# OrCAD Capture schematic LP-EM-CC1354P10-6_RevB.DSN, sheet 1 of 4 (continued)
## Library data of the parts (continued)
L12 L13 = INDUCTOR: INDUCTOR, RF, CHIP, NON-MAGNETIC CORE, 3.7nH, -0.1nH/+0.1nH, 0.4A, -55DEGC/+125DEGC, 0201, SMD; ALT_SYMBOLS: INDC0603X33A2L,INDC0603X33A2M; Additional Datasheet URL: https://search.murata.co.jp/Ceramy/image/img/P02/JELF243C-0015.pdf; AutoDoc File: https://notefied-dynamic-precision.com/DB/Apps/Desktop/Item/Object.aspx?id=97117; BU Name: DYNAMIC PRECISION GDANSK; Budget Currency: EUR; Budget Price: 0.03371; Client Status: UNDER_REVIEW; Core Material: NON-MAGNETIC; Country of Origin: Missing Info; Datasheet URL: https://www.murata.com/-/media/webrenewal/support/library/catalog/products/inductor/chip/o05e.ashx?la=en-gb; Datasheet URL 1: http://psearch.murata.com/inductor/product/LQP03TN2N4B02%23.pdf; Datasheet URL 2: http://www.murata.com/~/media/webrenewal/support/library/catalog/products/inductor/chip/o05e.ashx; Frequency: 6GHz; Mass: 0.0002g; Max Oper Temp: +125DEGC; Max Tol: +0.1nH; Maximum Operating Temperature: +125DEGC; Maximum Tolerance: +0.1nH; Min Oper Temp: -55DEGC; Min Tol: -0.1nH; Minimum Operating Temperature: -55DEGC; Minimum Tolerance: -0.1nH; Mounting Type: SMD; NOTEfied URL: https://notefied-dynamic-precision.com/NOTEfiedWebInterface/part/show?partNumber=03-06940; PCB Package: 0201; Packing Size: 50000; Packing Type: Tape & Reel; Part Number: 03-06940; Part Type: Inductor|RF|CHIP|0201; ROHS: Compliant; Resistance: 0.3; Revision: R020; RoHS Status: ROHS_COMPLIANT; Rtd Current: 0.5A; Status: Released; Texas Part Status: Under Review; Type: Inductor; Vendor: MURATA; Vendor Part Number: LQP03TN3N7B02J; Vendor Part Status: Active; Weight: 0.0002g
L14 = INDUCTOR: INDUCTOR, RF, CHIP, NON-MAGNETIC CORE, 3.4nH, -0.1nH/+0.1nH, 0.45A, -55DEGC/+125DEGC, 0201, SMD; ALT_SYMBOLS: INDC0603X33A2L,INDC0603X33A2M; Additional Datasheet URL: https://search.murata.co.jp/Ceramy/image/img/P02/JELF243C-0015.pdf; AutoDoc File: https://notefied-dynamic-precision.com/DB/Apps/Desktop/Item/Object.aspx?id=97103; BU Name: DYNAMIC PRECISION GDANSK; Budget Currency: EUR; Budget Price: 0.03371; Client Status: UNDER_REVIEW; Core Material: NON-MAGNETIC; Country of Origin: Missing Info; Datasheet URL: https://www.murata.com/-/media/webrenewal/support/library/catalog/products/inductor/chip/o05e.ashx?la=en-gb; Datasheet URL 1: http://psearch.murata.com/inductor/product/LQP03TN1N0B02%23.pdf; Datasheet URL 2: http://www.murata.com/~/media/webrenewal/support/library/catalog/products/inductor/chip/o05e.ashx; Frequency: 7GHz; Mass: 0.0002g; Max Oper Temp: +125DEGC; Maximum Operating Temperature: +125DEGC; Maximum Tolerance: +0.1nH; Min Oper Temp: -55DEGC; Min Tol: -0.1nH; Minimum Operating Temperature: -55DEGC; Minimum Tolerance: -0.1nH; Mounting Type: SMD; NOTEfied URL: https://notefied-dynamic-precision.com/NOTEfiedWebInterface/part/show?partNumber=03-06937; PCB Package: 0201; Packing Size: 50000; Packing Type: Tape & Reel; Part Number: 03-06937; Part Type: Inductor|RF|CHIP|0201; REACH/SVHC Compliance: Compliant; REACH/SVHC Details: SVHC List Version Jun 27, 2018; REACH/SVHC Source: REACH Declaration; REACH/SVHC Status: Unaffected; ROHS: Compliant; Resistance: 0.25; Revision: R021; RoHS Status: ROHS_COMPLIANT; Rtd Current: 0.75A; Status: Released; Texas Part Status: Under Review; Type: Inductor; Vendor: MURATA; Vendor Part Number: LQP03TN3N4B02J; Vendor Part Status: Active; Weight: 0.0002g
L15 = INDUCTOR: INDUCTOR, RF, CHIP, NON-MAGNETIC CORE, 3.9nH, -0.1nH/+0.1nH, Ir:0.5A, -55DEGC/+125DEGC, 0201, SMD; ALT_SYMBOLS: IND_LQP03HQ_A2L,IND_LQP03HQ_A2M; Additional Datasheet URL: https://www.murata.com/en-us/products/productdetail?partno=LQP03HQ3N9B02%23; Budgetary Price: 0.0576 USD; Country of Origin: China,Japan,Malaysia,United Kingdom,Vietnam; Datasheet URL: https://search.murata.co.jp/Ceramy/image/img/P02/JELF243C-0021.pdf; Frequency: 7GHz; Lead Time: 11; Mass: 0.00022g; Maximum Operating Temperature: +125DEGC; Maximum Tolerance: +0.1nH; Minimum Operating Temperature: -55DEGC; Minimum Tolerance: -0.1nH; Mounting Type: SMD; NOTEfied URL: https://notefied-dynamic-precision.com/NOTEfiedWebInterface/part/show?partNumber=03-07901; PCB Package: 0201; Packing Size: 15000; Packing Type: Tape & Reel; Part Number: 03-07901; Part Type: Inductor|RF|CHIP|0201; REACH/SVHC Compliance: Compliant; REACH/SVHC Details: SVHC List Version Jan 23, 2024 (240); REACH/SVHC Source: REACH Declaration; REACH/SVHC Status: Unaffected; ROHS: Compliant; Rated Current: 0.5A; Resistance: 0.17; Revision: R033; Status: Released; Texas Part Status: Under Review; Type: Inductor; Vendor: MURATA; Vendor Part Number: LQP03HQ3N9B02D; Vendor Part Status: Active
L27 L34 L43 = INDUCTOR: INDUCTOR, RF, CHIP, NON-MAGNETIC CORE, 6.8nH, -3%/+3%, 0.3A, -55DEGC/+125DEGC, 0201, SMD; ALT_SYMBOLS: INDC0603X33A2L,INDC0603X33A2M; Additional Datasheet URL: https://www.murata.com/en-us/products/productdetail?partno=LQP03TN6N8HZ2%23; Country of Origin: Missing Info; Datasheet URL: https://search.murata.co.jp/Ceramy/image/img/P02/JELF243C-9101.pdf; Frequency: 3.9GHz; Mass: 0.0002g; Maximum Operating Temperature: +125DEGC; Maximum Tolerance: +3%; Minimum Operating Temperature: -55DEGC; Minimum Tolerance: -3%; Mounting Type: SMD; NOTEfied URL: https://notefied-dynamic-precision.com/NOTEfiedWebInterface/part/show?partNumber=03-06950; PCB Package: 0201; Packing Size: 50000; Packing Type: Tape & Reel; Part Number: 03-06950; Part Type: Inductor|RF|CHIP|0201; ROHS: Compliant; Rated Current: 0.3A; Resistance: 0.6; Revision: R036; Status: Released; Texas Part Status: Under Review; Type: Inductor; Vendor: MURATA; Vendor Part Number: LQP03TN6N8HZ2J; Vendor Part Status: Active
L35 L36 = INDUCTOR: INDUCTOR, RF, CHIP, NON-MAGNETIC CORE, 2.4nH, -0.1nH/+0.1nH, 0.5A, -55DEGC/+125DEGC, 0201, SMD; ALT_SYMBOLS: INDC0603X33A2L,INDC0603X33A2M; Additional Datasheet URL: https://www.murata.com/en-us/products/productdetail?partno=LQP03TN2N4B02%23; Country of Origin: Missing Info; Datasheet URL: https://search.murata.co.jp/Ceramy/image/img/P02/JELF243C-0015.pdf; Frequency: 10GHz; Mass: 0.0002g; Maximum Operating Temperature: +125DEGC; Maximum Tolerance: +0.1nH; Minimum Operating Temperature: -55DEGC; Minimum Tolerance: -0.1nH; Mounting Type: SMD; NOTEfied URL: https://notefied-dynamic-precision.com/NOTEfiedWebInterface/part/show?partNumber=03-06927; PCB Package: 0201; Packing Size: 50000; Packing Type: Tape & Reel; Part Number: 03-06927; Part Type: Inductor|RF|CHIP|0201; ROHS: Compliant; Rated Current: 0.5A; Resistance: 0.2; Revision: R036; Status: Released; Texas Part Status: Under Review; Type: Inductor; Vendor: MURATA; Vendor Part Number: LQP03TN2N4B02J; Vendor Part Status: Active
L37 L39 = INDUCTOR: INDUCTOR, RF, CHIP, NON-MAGNETIC CORE, 3nH, -0.1nH/+0.1nH, Ir:0.6A, -55DEGC/+125DEGC, 0201, SMD; ALT_SYMBOLS: IND_LQP03HQ_A2L,IND_LQP03HQ_A2M; Additional Datasheet URL: https://www.murata.com/en-us/products/productdetail?partno=LQP03HQ3N0B02%23; Budgetary Price: 0.02729 USD; Country of Origin: China,Japan,Malaysia,United Kingdom,Vietnam; Datasheet URL: https://search.murata.co.jp/Ceramy/image/img/P02/JELF243C-0021.pdf; Frequency: 8GHz; Mass: 0.00022g; Maximum Operating Temperature: +125DEGC; Maximum Tolerance: +0.1nH; Minimum Operating Temperature: -55DEGC; Minimum Tolerance: -0.1nH; Mounting Type: SMD; NOTEfied URL: https://notefied-dynamic-precision.com/NOTEfiedWebInterface/part/show?partNumber=03-08790; PCB Package: 0201; Packing Size: 15000; Packing Type: Tape & Reel; Part Number: 03-08790; Part Type: Inductor|RF|CHIP|0201; REACH/SVHC Compliance: Compliant; REACH/SVHC Details: SVHC List Version Jan 23, 2024 (240); REACH/SVHC Source: REACH Declaration; REACH/SVHC Status: Unaffected; ROHS: Compliant; Rated Current: 0.6A; Resistance: 0.12; Revision: R008; Status: Released; Texas Part Status: Under Review; Type: Inductor; Vendor: MURATA; Vendor Part Number: LQP03HQ3N0B02D; Vendor Part Status: Active
L40 L45 = INDUCTOR: INDUCTOR, RF, CHIP, NON-MAGNETIC CORE, 10nH, -3%/+3%, 0.25A, -55DEGC/+125DEGC, 0201, SMD; ALT_SYMBOLS: INDC0603X33A2L,INDC0603X33A2M; Additional Datasheet URL: https://www.murata.com/en-us/products/productdetail?partno=LQP03TN10NHZ2%23; Country of Origin: Missing Info; Datasheet URL: https://search.murata.co.jp/Ceramy/image/img/P02/JELF243C-9101.pdf; Frequency: 3.2GHz; Mass: 0.0002g; Maximum Operating Temperature: +125DEGC; Maximum Tolerance: +3%; Minimum Operating Temperature: -55DEGC; Minimum Tolerance: -3%; Mounting Type: SMD; NOTEfied URL: https://notefied-dynamic-precision.com/NOTEfiedWebInterface/part/show?partNumber=03-06954; PCB Package: 0201; Packing Size: 50000; Packing Type: Tape & Reel; Part Number: 03-06954; Part Type: Inductor|RF|CHIP|0201; ROHS: Compliant; Rated Current: 0.25A; Resistance: 0.7; Revision: R036; Status: Released; Texas Part Status: Under Review; Type: Inductor; Vendor: MURATA; Vendor Part Number: LQP03TN10NHZ2J; Vendor Part Status: Active
L41 L44 = INDUCTOR: INDUCTOR, RF, CHIP, NON-MAGNETIC CORE, 3.4nH, -0.1nH/+0.1nH, 0.45A, -55DEGC/+125DEGC, 0201, SMD; ALT_SYMBOLS: INDC0603X33A2L,INDC0603X33A2M; Additional Datasheet URL: https://www.murata.com/en-us/products/productdetail?partno=LQP03TN3N4B02%23; Country of Origin: Missing Info; Datasheet URL: https://search.murata.co.jp/Ceramy/image/img/P02/JELF243C-0015.pdf; Frequency: 7GHz; Mass: 0.0002g; Maximum Operating Temperature: +125DEGC; Maximum Tolerance: +0.1nH; Minimum Operating Temperature: -55DEGC; Minimum Tolerance: -0.1nH; Mounting Type: SMD; NOTEfied URL: https://notefied-dynamic-precision.com/NOTEfiedWebInterface/part/show?partNumber=03-06937; PCB Package: 0201; Packing Size: 50000; Packing Type: Tape & Reel; Part Number: 03-06937; Part Type: Inductor|RF|CHIP|0201; REACH/SVHC Compliance: Compliant; REACH/SVHC Details: SVHC List Version Jan 23, 2024 (240); REACH/SVHC Source: REACH Declaration; REACH/SVHC Status: Unaffected; ROHS: Compliant; Rated Current: 0.45A; Resistance: 0.25; Revision: R037; Status: Released; Texas Part Status: Under Review; Type: Inductor; Vendor: MURATA; Vendor Part Number: LQP03TN3N4B02J; Vendor Part Status: Active
L42 = INDUCTOR: INDUCTOR, RF, CHIP, NON-MAGNETIC CORE, 22nH, -3%/+3%, 0.15A, -55DEGC/+125DEGC, 0201, SMD; ALT_SYMBOLS: INDC0603X33A2L,INDC0603X33A2M; Additional Datasheet URL: https://www.murata.com/en-us/products/productdetail?partno=LQP03TN22NHZ2%23; Country of Origin: Missing Info; Datasheet URL: https://search.murata.co.jp/Ceramy/image/img/P02/JELF243C-9101.pdf; Frequency: 2.2GHz; Mass: 0.0002g; Maximum Operating Temperature: +125DEGC; Maximum Tolerance: +3%; Minimum Operating Temperature: -55DEGC; Minimum Tolerance: -3%; Mounting Type: SMD; NOTEfied URL: https://notefied-dynamic-precision.com/NOTEfiedWebInterface/part/show?partNumber=03-06962; PCB Package: 0201; Packing Size: 50000; Packing Type: Tape & Reel; Part Number: 03-06962; Part Type: Inductor|RF|CHIP|0201; ROHS: Compliant; Rated Current: 0.15A; Resistance: 1.9; Revision: R036; Status: Released; Texas Part Status: Under Review; Type: Inductor; Vendor: MURATA; Vendor Part Number: LQP03TN22NHZ2J; Vendor Part Status: Active
R1 = RESISTOR: RESISTOR, THICK FILM, 100k, -5%/+5%, 0.063W, 50V, -55DEGC/+155DEGC, 0402, SMD; Additional Datasheet URL: https://www.vishay.com/en/product/20035/; AutoDoc File: https://notefied-dynamic-precision.com/DB/Apps/Desktop/Item/Object.aspx?id=114565; BU Name: TEXAS INSTRUMENTS NORWAY; Budget Currency: EUR; Budget Price: 0.014; Budgetary Price: 0.014 EUR; Client Status: UNDER_REVIEW; Country of Origin: China,Israel; Datasheet URL: https://www.vishay.com/docs/20035/dcrcwe3.pdf; Datasheet URL 1: http://www.vishay.com/docs/20035/dcrcwe3.pdf; Datasheet URL 2: N/A; Definied Quality: INDUSTRIAL; Esd Level: N/A; Lead Time: 18; LifeCycle Status: ACTIVE; MPN: RESISTOR_0402_100k_+/-1%_50V_0.063W_M_+/-100PPM; MPN Status: ACTIVE; MSL: N/A; MTBF: N/A; MTBF Standard: N/A; Manufacturer: MANUFACTURER SELECTION; Mass: 0.00065g; Max Oper Temp: +155DEGC; Max TC: +200PPM/DEGC; Max Tol: +5%; Maximum Operating Temperature: +155DEGC; Maximum Temperature Coefficient: +200PPM/DEGC; Maximum Tolerance: +5%; Min Oper Temp: -55DEGC; Min TC: -200PPM/DEGC; Min Tol: -5%; Minimum Operating Temperature: -55DEGC; Minimum Temperature Coeficient: -200PPM/DEGC; Minimum Tolerance: -5%; Mounting Type: SMD; NOTE Status: PREFERRED; NOTEfied URL: https://notefied-dynamic-precision.com/NOTEfiedWebInterface/part/show?partNumber=01-22492; Notes: Standard item: Duplicate Reason: custom footprint for TEXAS INSTRUMENTS NORWAY.; Old Footprint: RESC1005X40N; PCB Package: 0402; Packing Size: 10000; Packing Type: Tape & Reel; Part Number: 01-22492; Part Type: Resistor|0402|STANDARD; REACH/SVHC Compliance: Compliant; REACH/SVHC Details: SVHC List Version Jan 23, 2024 (240); REACH/SVHC Source: REACH Declaration & Material Declaration; REACH/SVHC Status: Unaffected; REACH/SVHC_COMPLIANCE: COMPLIANT; REACH/SVHC_DETAILS: SVHC LIST VERSION Jun 20, 2016; REACH/SVHC_SOURCE: MATERIAL DECLARATION; REACH/SVHC_STATUS: UNAFFECTED; ROHS: Exempt; Rated Current: N/A; Rated Power: 0.063W; Rated Voltage: 50V; Resistor Type: THICK FILM; Revision: R040; RoHS Status: ROHS_COMPLIANT; Rtd Current: N/A; Rtd Power: 0.063W; Rtd Voltage: 50V; Status: Released; Texas Part Status: Under Review; Type: Resistor; Vendor: VISHAY; Vendor Part Number: CRCW0402100KJNED; Vendor Part Status: Active; Weight: 0.00065g
R41 = RESISTOR: RESISTOR, THICK FILM, 0, 0R/+0.02R, 0.063W, 1.5A, -55DEGC/+155DEGC, 0402, SMD; Additional Datasheet URL: N/A; Budgetary Price: 0.007 EUR; Country of Origin: Israel; Datasheet URL: https://www.vishay.com/docs/20035/dcrcwe3.pdf; Lead Time: 14; Mass: 0.00065g; Maximum Operating Temperature: +155DEGC; Maximum Temperature Coefficient: N/A; Maximum Tolerance: +0.02R; Minimum Operating Temperature: -55DEGC; Minimum Temperature Coeficient: N/A; Minimum Tolerance: 0R; Mounting Type: SMD; NOTEfied URL: https://notefied-dynamic-precision.com/NOTEfiedWebInterface/part/show?partNumber=01-22495; Notes: Standard item: Duplicate Reason: custom footprint for TEXAS INSTRUMENTS NORWAY.; PCB Package: 0402; Packing Size: 10000; Packing Type: Tape & Reel; Part Number: 01-22495; Part Type: Resistor|0402|JUMPER; REACH/SVHC Compliance: Compliant; REACH/SVHC Details: SVHC List Version Jul 07, 2017; REACH/SVHC Source: REACH Declaration; REACH/SVHC Status: Unaffected; ROHS: Exempt; Rated Current: 1.5A; Rated Power: 0.063W; Rated Voltage: N/A; Resistor Type: THICK FILM; Revision: R037; Status: Released; Texas Part Status: Under Review; Type: Resistor; Vendor: VISHAY; Vendor Part Number: CRCW04020000Z0ED; Vendor Part Status: Active
R42 = RESISTOR: RESISTOR, THICK FILM, JUMPER, 0, 0R/+0.02R, 0.063W, 1.5A, -55DEGC/+155DEGC, 0402, SMD; Additional Datasheet URL: https://www.vishay.com/en/product/20035/; Budgetary Price: 0.007 EUR; Country of Origin: China,Israel,Taiwan; Datasheet URL: https://www.vishay.com/docs/20035/dcrcwe3.pdf; Lead Time: 14; Mass: 0.00065g; Maximum Operating Temperature: +155DEGC; Maximum Temperature Coefficient: N/A; Maximum Tolerance: +0.02R; Minimum Operating Temperature: -55DEGC; Minimum Temperature Coeficient: N/A; Minimum Tolerance: 0R; Mounting Type: SMD; NOTEfied URL: https://notefied-dynamic-precision.com/NOTEfiedWebInterface/part/show?partNumber=01-22495; Notes: Standard item: Duplicate Reason: custom footprint for TEXAS INSTRUMENTS NORWAY.; PCB Package: 0402; Packing Size: 10000; Packing Type: Tape & Reel; Part Number: 01-22495; Part Type: Resistor|0402|JUMPER; REACH/SVHC Compliance: Compliant; REACH/SVHC Details: SVHC List Version Jan 23, 2024 (240); REACH/SVHC Source: REACH Declaration & Material Declaration; REACH/SVHC Status: Unaffected; ROHS: Exempt; Rated Current: 1.5A; Rated Power: 0.063W; Rated Voltage: N/A; Resistor Type: THICK FILM; Revision: R047; Status: Released; Texas Part Status: Under Review; Type: Resistor; Vendor: VISHAY; Vendor Part Number: CRCW04020000Z0ED; Vendor Part Status: Active
U1 = IC_RF_CC1354P106T0RSK_VQFN64: IC, CUSTOM, TEXAS INSTRUMENTS, CC1354P106T0RSK, VQFN64-EP, SMD; ALT_SYMBOLS: QFNFC40P800X800X100-65A2L,QFNFC40P800X800X100-65A2M; Additional Datasheet URL: https://www.ti.com/; Country of Origin: Missing Info; Datasheet URL: N/A; Mass: N/A; Maximum Operating Temperature: N/A; Minimum Operating Temperature: N/A; Mounting Type: SMD; NOTEfied URL: https://notefied-dynamic-precision.com/NOTEfiedWebInterface/part/show?partNumber=18-36708; Notes: Custom component.; PCB Package: VQFN64-EP; Packing Size: N/A; Packing Type: Missing Info; Part Number: 18-36708; Part Type: IC|CUSTOM; REACH/SVHC Details: SVHC List Version; ROHS: Missing Info; Revision: R015; Status: Released; Texas Part Status: Under Review; Type: IC; Vendor: TEXAS INSTRUMENTS; Vendor Part Status: Preliminary
U2 = IC_RF_SKY13317-373LF_MLP8: IC, ANALOG, RF, SWITCH,  20MHz TO 6GHz, SP3T, VCONTROL:0V TO 5V, MLP8-EP, SMD; Additional Datasheet URL: https://www.skyworksinc.com/en/Products/switches/SKY13317-373LF; AutoDoc File: https://notefied-dynamic-precision.com/DB/Apps/Desktop/Item/Object.aspx?id=117700; BU Name: DYNAMIC PRECISION GDANSK; Budgetary Price: 0.686 USD; CLASS: IO; Client Status: UNDER_REVIEW; Country of Origin: Missing Info; Datasheet URL: https://www.skyworksinc.com/-/media/SkyWorks/Documents/Products/301-400/SKY13317-373LF_200914L.pdf; Datasheet URL 1: http://www.skyworksinc.com/uploads/documents/SKY13317_373LF_200914K.pdf; Datasheet URL 2: N/A; Frequency: 20MHz TO 6GHz; Lead Time: 13; Mass: N/A; Max Oper Temp: +100DEGC; Maximum Operating Temperature: +100DEGC; Min Oper Temp: -40DEGC; Minimum Operating Temperature: -40DEGC; Mounting Type: SMD; NOTEfied URL: https://notefied-dynamic-precision.com/NOTEfiedWebInterface/part/show?partNumber=18-33966; PCB Package: MLP8-EP; Packing Size: N/A; Packing Type: Tape & Reel; Part Number: 18-33966; Part Type: IC|ANALOG|RF|SWITCH; REACH/SVHC Compliance: Compliant; REACH/SVHC Details: SVHC List Version Jan 23, 2024 (240); REACH/SVHC Source: RoHS & REACH Declaration; REACH/SVHC Status: Unaffected; ROHS: Compliant; Rated Voltage: 0V TO 5V; Revision: R030; RoHS Status: ROHS_COMPLIANT; Rtd Voltage: 0V TO 5V; Status: Released; Texas Part Status: Under Review; Type: IC; Vendor: SKYWORKS; Vendor Part Number: SKY13317-373LF; Vendor Part Status: Active
Y1 = XTAL: CRYSTAL, RESONATOR, 32.768kHz, -40DEGC/+125DEGC, SMD; ALT_SYMBOLS: XTAL_TZ3581F_A2L,XTAL_TZ3581F_A2M; Additional Datasheet URL: https://www.taisaw.com/en/index.php; Capacitance: 7pF; Country of Origin: Missing Info; Datasheet URL: N/A; Maximum Operating Temperature: +125DEGC; Maximum Stability: N/A; Maximum Tolerance: +20PPM; Minimum Operating Temperature: -40DEGC; Minimum Stability: N/A; Minimum Tolerance: -20PPM; Mounting Type: SMD; NOTEfied URL: https://notefied-dynamic-precision.com/NOTEfiedWebInterface/part/show?partNumber=12-01571; Packing Size: 336; Packing Type: Tray; Part Number: 12-01571; Part Type: Crystal|RESONATOR; REACH/SVHC Compliance: Missing Info; REACH/SVHC Details: N/A; REACH/SVHC Source: N/A; REACH/SVHC Status: Missing Info; ROHS: Compliant; Revision: R013; Status: Released; Texas Part Status: Under Review; Type: Crystal; Vendor: TAI-SAW; Vendor Part Number: TZ3581F; Vendor Part Status: Active
Y2 = XTAL_4PINS_1_3: CRYSTAL, RESONATOR, 48MHz, -16PPM/+18PPM, -40DEGC/+105DEGC, 2016, SMD; ALT_SYMBOLS: OSCCC200X160X50-4A2L,OSCCC200X160X50-4A2M; Additional Datasheet URL: https://www.taisaw.com/en/index.php; Budgetary Price: 0.96834 USD; Capacitance: 7pF; Country of Origin: Missing Info; Datasheet URL: N/A; Lead Time: 1; Mass: 0.0057g; Maximum Operating Temperature: +105DEGC; Maximum Stability: +18PPM; Maximum Tolerance: +5PPM; Minimum Operating Temperature: -40DEGC; Minimum Stability: -16PPM; Minimum Tolerance: -5PPM; Mounting Type: SMD; NOTEfied URL: https://notefied-dynamic-precision.com/NOTEfiedWebInterface/part/show?partNumber=12-01572; PCB Package: 2016; Packing Size: 3000; Packing Type: Tape & Reel; Part Number: 12-01572; Part Type: Crystal|RESONATOR; REACH/SVHC Compliance: Missing Info; REACH/SVHC Details: N/A; REACH/SVHC Source: N/A; REACH/SVHC Status: Missing Info; ROHS: Compliant; Revision: R015; Status: Released; Texas Part Status: Under Review; Type: Crystal; Vendor: TAI-SAW; Vendor Part Number: TZ3780AAAO44; Vendor Part Status: Active
Z1 = CAPACITOR: CAPACITOR, CERAMIC C0G/NP0, 2.5pF, 50V, -0.1pF/+0.1pF, -55DEGC/+125DEGC, 0201, SMD; ALT_SYMBOLS: CAPC0603X35B2L,CAPC0603X35B2M; Additional Datasheet URL: https://www.murata.com/en-us/products/productdetail?partno=GRM0335C1H2R5BA01%23; Budgetary Price: 0.00215 USD; Country of Origin: China,Japan; Datasheet URL: https://search.murata.co.jp/Ceramy/image/img/A01X/G101/ENG/GRM0335C1H2R5BA01-01A.pdf; Dielectric Type: C0G/NP0; Lead Time: 84; Mass: 0.00033g; Maximum Operating Temperature: +125DEGC; Maximum Tolerance: +0.1pF; Minimum Operating Temperature: -55DEGC; Minimum Tolerance: -0.1pF; Mounting Type: SMD; NOTEfied URL: https://notefied-dynamic-precision.com/NOTEfiedWebInterface/part/show?partNumber=02-06139; PCB Package: 0201; Packing Size: 50000; Packing Type: Tape & Reel; Part Number: 02-06139; Part Type: Capacitor|CERAMIC|0201|STANDARD; REACH/SVHC Compliance: Compliant; REACH/SVHC Details: SVHC List Version Jan 23, 2024 (240); REACH/SVHC Source: REACH Declaration; REACH/SVHC Status: Unaffected; ROHS: Compliant; Rated Voltage: 50V; Revision: R042; Status: Released; Texas Part Status: Under Review; Type: Capacitor; Vendor: MURATA; Vendor Part Number: GRM0335C1H2R5BA01J; Vendor Part Status: Active
Z2 = CAPACITOR: CAPACITOR, CERAMIC C0G/NP0, 47pF, 50V, -5%/+5%, -55DEGC/+125DEGC, 0201, SMD; ALT_SYMBOLS: CAPC0603X35B2L,CAPC0603X35B2M; Additional Datasheet URL: https://www.murata.com/en-us/products/productdetail?partno=GRM0335C1H470JA01%23; Budgetary Price: 0.0024 USD; Country of Origin: China,Japan,Philippines; Datasheet URL: https://search.murata.co.jp/Ceramy/image/img/A01X/G101/ENG/GRM0335C1H470JA01-01A.pdf; Dielectric Type: C0G/NP0; Lead Time: 11; Mass: 0.00033g; Maximum Operating Temperature: +125DEGC; Maximum Tolerance: +5%; Minimum Operating Temperature: -55DEGC; Minimum Tolerance: -5%; Mounting Type: SMD; NOTEfied URL: https://notefied-dynamic-precision.com/NOTEfiedWebInterface/part/show?partNumber=02-09159; PCB Package: 0201; Packing Size: 15000; Packing Type: Tape & Reel; Part Number: 02-09159; Part Type: Capacitor|CERAMIC|0201|STANDARD; REACH/SVHC Compliance: Compliant; REACH/SVHC Details: SVHC List Version Jan 23, 2024 (240); REACH/SVHC Source: REACH Declaration; REACH/SVHC Status: Unaffected; ROHS: Compliant; Rated Voltage: 50V; Revision: R025; Status: Released; Texas Part Status: Under Review; Type: Capacitor; Vendor: MURATA; Vendor Part Number: GRM0335C1H470JA01D; Vendor Part Status: Active
Z3 = CAPACITOR: CAPACITOR, CERAMIC C0G/NP0, 5.6pF, 50V, -0.1pF/+0.1pF, -55DEGC/+125DEGC, 0201, SMD; ALT_SYMBOLS: CAPC0603X35B2L,CAPC0603X35B2M; Additional Datasheet URL: https://search.murata.co.jp/Ceramy/image/img/A01X/G101/ENG/GRM0335C1H5R6BA01-01A.pdf; Budgetary Price: 0.00272 USD; Country of Origin: Missing Info; Datasheet URL: https://www.murata.com/-/media/webrenewal/support/library/catalog/products/capacitor/mlcc/c02e.ashx?la=en-gb; Dielectric Type: C0G/NP0; Lead Time: 11; Mass: 0.00033g; Maximum Operating Temperature: +125DEGC; Maximum Tolerance: +0.1pF; Minimum Operating Temperature: -55DEGC; Minimum Tolerance: -0.1pF; Mounting Type: SMD; NOTEfied URL: https://notefied-dynamic-precision.com/NOTEfiedWebInterface/part/show?partNumber=02-06170; PCB Package: 0201; Packing Size: 50000; Packing Type: Tape & Reel; Part Number: 02-06170; Part Type: Capacitor|CERAMIC|0201|STANDARD; REACH/SVHC Compliance: Compliant; REACH/SVHC Details: SVHC List Version Jul 7, 2017; REACH/SVHC Source: REACH Declaration; REACH/SVHC Status: Unaffected; ROHS: Compliant; Rated Voltage: 50V; Revision: R025; Status: Released; Texas Part Status: Under Review; Type: Capacitor; Vendor: MURATA; Vendor Part Number: GRM0335C1H5R6BA01J; Vendor Part Status: Active
Z4 = INDUCTOR: INDUCTOR, RF, CHIP, NON-MAGNETIC CORE, 27nH, -3%/+3%, 0.14A, -55DEGC/+125DEGC, 0201, SMD; ALT_SYMBOLS: INDC0603X33A2L,INDC0603X33A2M; Additional Datasheet URL: https://www.murata.com/en-us/products/productdetail?partno=LQP03TN27NHZ2%23; AutoDoc File: https://notefied-dynamic-precision.com/DB/Apps/Desktop/Item/Object.aspx?id=97154; BU Name: DYNAMIC PRECISION GDANSK; Budget Currency: N/A; Budget Price: N/A; Client Status: UNDER_REVIEW; Core Material: NON-MAGNETIC; Country of Origin: Missing Info; Datasheet URL: https://search.murata.co.jp/Ceramy/image/img/P02/JELF243C-9101.pdf; Datasheet URL 1: http://psearch.murata.com/inductor/product/LQP03TN27NHZ2%23.pdf; Datasheet URL 2: http://www.murata.com/~/media/webrenewal/support/library/catalog/products/inductor/chip/o05e.ashx; Frequency: 2GHz; Mass: 0.0002g; Max Oper Temp: +125DEGC; Max Tol: +3%; Maximum Operating Temperature: +125DEGC; Maximum Tolerance: +3%; Min Oper Temp: -55DEGC; Min Tol: -3%; Minimum Operating Temperature: -55DEGC; Minimum Tolerance: -3%; Mounting Type: SMD; NOTEfied URL: https://notefied-dynamic-precision.com/NOTEfiedWebInterface/part/show?partNumber=03-06964; PCB Package: 0201; Packing Size: 50000; Packing Type: Tape & Reel; Part Number: 03-06964; Part Type: Inductor|RF|CHIP|0201; ROHS: Compliant; Rated Current: 0.14A; Resistance: 2.3; Revision: R036; RoHS Status: ROHS_COMPLIANT; Rtd Current: 0.14A; Status: Released; Texas Part Status: Under Review; Type: Inductor; Vendor: MURATA; Vendor Part Number: LQP03TN27NHZ2J; Vendor Part Status: Active; Weight: 0.0002g
Z7 = CAPACITOR: CAPACITOR, CERAMIC C0G/NP0, 3.9pF, 50V, -0.1pF/+0.1pF, -55DEGC/+125DEGC, 0201, SMD; ALT_SYMBOLS: CAPC0603X35B2L,CAPC0603X35B2M; Additional Datasheet URL: https://www.murata.com/en-us/products/productdetail?partno=GRM0335C1H3R9BA01%23; Budgetary Price: 0.00272 USD; Country of Origin: China,Japan,Philippines; Datasheet URL: https://search.murata.co.jp/Ceramy/image/img/A01X/G101/ENG/GRM0335C1H3R9BA01-01A.pdf; Dielectric Type: C0G/NP0; Lead Time: 11; Mass: 0.00033g; Maximum Operating Temperature: +125DEGC; Maximum Tolerance: +0.1pF; Minimum Operating Temperature: -55DEGC; Minimum Tolerance: -0.1pF; Mounting Type: SMD; NOTEfied URL: https://notefied-dynamic-precision.com/NOTEfiedWebInterface/part/show?partNumber=02-06153; PCB Package: 0201; Packing Size: 50000; Packing Type: Tape & Reel; Part Number: 02-06153; Part Type: Capacitor|CERAMIC|0201|STANDARD; REACH/SVHC Compliance: Compliant; REACH/SVHC Details: SVHC List Version Jan 23, 2024 (240); REACH/SVHC Source: REACH Declaration; REACH/SVHC Status: Unaffected; ROHS: Compliant; Rated Voltage: 50V; Revision: R041; Status: Released; Texas Part Status: Under Review; Type: Capacitor; Vendor: MURATA; Vendor Part Number: GRM0335C1H3R9BA01J; Vendor Part Status: Active
Z8 = INDUCTOR: INDUCTOR, RF, CHIP, NON-MAGNETIC CORE, 0.6nH, -0.1nH/+0.1nH, 0.85A, -55DEGC/+125DEGC, 0201, SMD; ALT_SYMBOLS: INDC0603X33A2L,INDC0603X33A2M; Additional Datasheet URL: https://www.murata.com/en-us/products/productdetail?partno=LQP03TN0N6B02%23; Country of Origin: Missing Info; Datasheet URL: https://search.murata.co.jp/Ceramy/image/img/P02/JELF243C-0015.pdf; Frequency: 20GHz; Mass: 0.0002g; Maximum Operating Temperature: +125DEGC; Maximum Tolerance: +0.1nH; Minimum Operating Temperature: -55DEGC; Minimum Tolerance: -0.1nH; Mounting Type: SMD; NOTEfied URL: https://notefied-dynamic-precision.com/NOTEfiedWebInterface/part/show?partNumber=03-06909; PCB Package: 0201; Packing Size: 50000; Packing Type: Tape & Reel; Part Number: 03-06909; Part Type: Inductor|RF|CHIP|0201; ROHS: Compliant; Rated Current: 0.85A; Resistance: 0.07; Revision: R037; Status: Released; Texas Part Status: Under Review; Type: Inductor; Vendor: MURATA; Vendor Part Number: LQP03TN0N6B02J; Vendor Part Status: Active
Z44 Z45 = RESISTOR: RESISTOR, THICK FILM, JUMPER, 0, 0R/+0.05R, 0.05W, 1A, -55DEGC/+155DEGC, 0201, SMD; ALT_SYMBOLS: RESC0603X35B2L,RESC0603X35B2M; Additional Datasheet URL: https://www.vishay.com/en/product/20052/; Budgetary Price: 0.00605 EUR; Country of Origin: China,Israel,Taiwan; Datasheet URL: https://www.vishay.com/docs/20052/crcw0201e3.pdf; Lead Time: 20; Mass: 0.000143039g; Maximum Operating Temperature: +155DEGC; Maximum Temperature Coefficient: N/A; Maximum Tolerance: +0.05R; Minimum Operating Temperature: -55DEGC; Minimum Temperature Coeficient: N/A; Minimum Tolerance: 0R; Mounting Type: SMD; NOTEfied URL: https://notefied-dynamic-precision.com/NOTEfiedWebInterface/part/show?partNumber=01-04043; PCB Package: 0201; Packing Size: 10000; Packing Type: Tape & Reel; Part Number: 01-04043; Part Type: Resistor|0201|JUMPER; REACH/SVHC Compliance: Compliant; REACH/SVHC Details: SVHC List Version Jan 23, 2024 (240); REACH/SVHC Source: REACH Declaration & Material Declaration; REACH/SVHC Status: Unaffected; ROHS: Exempt; Rated Current: 1A; Rated Power: 0.05W; Rated Voltage: N/A; Resistor Type: THICK FILM; Revision: R053; Status: Released; Texas Part Number: TEXAS_00014; Texas Part Status: Under Review; Type: Resistor; Vendor: VISHAY; Vendor Part Number: CRCW02010000Z0ED; Vendor Part Status: Active

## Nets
GND: C1.2 C2.2 C3.2 C4.2 C5.2 C6.2 C7.2 C8.2 C9.2 C11.1 C12.1 C14.1 C15.1 C31.1 C33.2 C34.2 C35.2 C37.1 C38.1 C50.2 C51.2 C52.2 C53.2 C54.2 C56.1 C59.2 C60.2 C61.2 C62.2 C63.2 CR1.1 J3.2 J3.3 J3.4 J3.5 U1.65(EGP) U2.9(EGP) Y2.2(GND) Y2.4(GND) Z3.1 Z4.2 Z8.2 ; also on sheet 2 3 4
VDDR: C1.1 C7.1 C8.1 L1.1 R42.2 U1.61(VDDR) U1.64(VDDR_RF)
VDDS: C2.1 C3.1 C4.1 C5.1 C6.1 FL1.1 R1.2 R41.2 U1.17(VDDS2) U1.30(VDDS3) U1.48(VDDS_DCDC) U1.60(VDDS)
DIO3_RF_PA: U2.3(V1) ; also on sheet 2
DIO34_RF_2G4: U2.7(V3) ; also on sheet 2
DIO35_RF_SUB1G: U2.6(V2) ; also on sheet 2
RX_TX: C11.2 C56.2 L12.1 L40.1 U1.7(RX_TX)
WMCU_RESET: C54.1 R1.1 U1.49(nRESET) ; also on sheet 2 3
WMCU_TCK: U1.33(JTAG_TCKC) ; also on sheet 2 3
WMCU_TMS: U1.32(JTAG_TSMC) ; also on sheet 2 3
WMCU_VDD: FL1.2 ; also on sheet 2 3
N3099875: C13.1 L11.1 L12.2 U1.1(2_4_GHZ_RF_P)
N3099951: C13.2 L13.2 L14.1
N3100073: C14.2 L14.2 L15.1
N3100081: C15.2 C16.1 L15.2
N3100105: C17.1 J3.1
N3100141: C12.2 L11.2 L13.1 U1.2(2_4_GHZ_RF_N)
N3100321: C17.2 C18.1 CR1.2 Z45.1
N3100543: C16.2 U2.8(RF3)
N3100575: C27.2 U2.5(RF2)
N3100757: L41.1 U1.3(SUB-1_GHZ_RF_P)
N3100925: L44.1 U1.4(SUB-1_GHZ_RF_N)
N3100985: C32.1 L34.1 L35.2 U1.5(TX_20DBM_P)
N3100993: C18.2 Z1.1
N3100997: C31.2 L34.2 L36.1 U1.6(TX_20DBM_N)
N3101199: C50.1 U1.8(X32K_Q1) Y1.1
N3101207: C51.1 U1.9(X32K_Q2) Y1.2
N3101223: C52.1 U1.63(X48M_P) Y2.1
N3101377: Z1.2 Z2.1 Z3.2 Z4.1
N3101433: A1.1 Z2.2
N3101449: C53.1 U1.62(X48M_N) Y2.3
N3101953: C62.1 U2.4(RF1) Z44.1
N3254079: L1.2 U1.47(DCDC_SW)
N3281348: C9.1 U1.31(DCOUPL)
N3492676: C27.1 L27.2 Z7.1
N3492704: Z7.2 Z8.1
N3493209: C57.1 C58.1 L40.2 L41.2 L42.1
N3493257: C57.2 C59.1 L43.1 L45.2
N3493329: C60.1 L27.1 L43.2
N3493341: C58.2 C61.1 L42.2 L44.2 L45.1
N3546372: C33.1 C34.1 L35.1 R41.1 R42.1
N3546508: C32.2 C35.1 L36.2 L37.1
N3546612: C37.2 L37.2 L39.1
N3546624: C38.2 C39.1 L39.2
N3546636: C39.2 Z44.2
N3547384: C63.1 U2.1(RFC) Z45.2

Not connected (* = marked no-connect by the designer): U2 2(NC)*

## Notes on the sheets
sheet 1
- Wireless MCU RF
- Wireless MCU IO block placed on page 2
- 5 dBm 2.4 GHz
- RF Control Truth Table
- DIO3  DIO34  DIO35
  Shutdown   0     0      0
  Sub 1 GHz  0     0      1
  2.4 GHz    0     1      0
  20dBm PA   1     0      0
- Wireless MCU IO
  section on page 2
- Pin 17
- Pin 30
- Pin 60
- Pin 61
- Pin 64
- Optimised for 868/915
  MHz dual-band match.
  See App Note SWRA640
  for more information
  on optimised 868 MHz
  and 915 MHz single
  band matching networks
- PA Path Optimizations
- R41       DNM           0
  R42       0             DNM
  Z44       0             1.5nH
  L37       3.0nH         1.8nH
  L39       3.0nH         1.6nH
  C35       DNM           DNM
  C37, C38  1.5pF         2.2pF
  C62       DNM           1.5pF
  Z1        2.5pF         4nH
  Z2        47pF          0
  Z3        DNM           DNM
  Z4        27nH          DNM
  CR1       TPD1E0B04DPY  DNM
- Reference
  Designator
- +10dBm TX
- +20dBm TX
- 2.4GHz
  +10dBm or +20dBm TX Path
- Z1-Z4 for
  antenna matching
